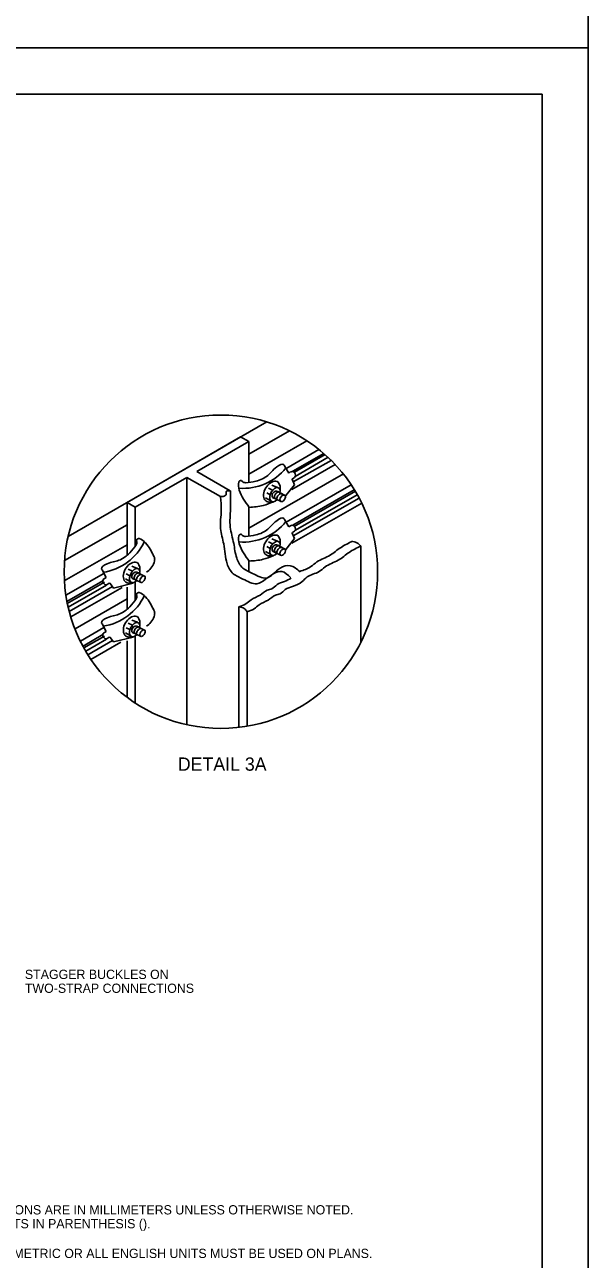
# Model space of a CAD drawing. Extents: x 650495 to 651400, y 297864 to 299646.
# Drawn here: x 651153.6 to 651336.3, y 298064.9 to 298465.1 of the extents above; entities that cross this region are included whole.
import ezdxf

# ---------------------------------------------------------------- set-up
doc = ezdxf.new("R2010")
doc.units = 0
for name, color, linetype in [('1', 7, 'Continuous'), ('2', 7, 'Continuous'), ('PLT-BNDY', 7, 'Continuous')]:
    doc.layers.add(name, color=color, linetype=linetype)

msp = doc.modelspace()

# ---------------------------------------------------------------- linework, layer by layer
at = {"layer": '1'}
for p in [(650535.31, 298442.63), (651321.31, 297878.63)]:
    msp.add_line(p, (651321.31, 298442.63), dxfattribs=at)
at = {"layer": '2'}
for p, q in [((651167.69, 298299.25), (651232.06, 298336.38)), ((651226.31, 298325.88), (651239.44, 298333.5)), ((651239.44, 298333.5), (651239.44, 298333.5)), ((651186.81, 298310.25), (651223.56, 298331.5)), ((651226.31, 298330), (651209.44, 298320.25)), ((651223.56, 298331.5), (651226.31, 298330)), ((651226.31, 298319.38), (651245.06, 298330.25)), ((651226.31, 298330), (651226.31, 298316.79)), ((651238.56, 298321.4), (651248.94, 298327.38)), ((651250.56, 298326.13), (651240.59, 298320.4)), ((651241.04, 298320.01), (651251.06, 298325.75)), ((651241.31, 298318.63), (651251.94, 298324.88)), ((651237.81, 298322.13), (651239.19, 298319.75)), ((651240.19, 298314.45), (651254.31, 298322.5)), ((651240.69, 298316.88), (651252.94, 298323.88)), ((651206.19, 298318.38), (651189.44, 298308.75)), ((651206.19, 298318.38), (651206.19, 298238.13)), ((651217.05, 298312.12), (651206.19, 298318.38)), ((651209.44, 298320.25), (651220.25, 298314.02)), ((651226.31, 298301.95), (651256.94, 298319.5)), ((651240.31, 298317.75), (651241.06, 298316)), ((651232.06, 298313.38), (651233.19, 298312.75)), ((651232.69, 298314.88), (651233.94, 298314.25)), ((651233.19, 298313.75), (651233.19, 298313.75)), ((651233.69, 298315.88), (651235.56, 298315.13)), ((651235.44, 298313.88), (651237.81, 298312.63)), ((651241.06, 298316), (651238.31, 298312.44)), ((651238.34, 298303.84), (651259.44, 298316)), ((651240.54, 298302.9), (651260.44, 298314.38)), ((651241, 298302.43), (651260.81, 298313.88)), ((651241.44, 298301.22), (651261.44, 298312.75)), ((651186.81, 298310.25), (651186.81, 298293.25)), ((651189.44, 298308.75), (651186.81, 298310.25)), ((651189.44, 298308.75), (651189.44, 298296.13)), ((651226.31, 298308.65), (651226.31, 298299.24)), ((651231.69, 298311.75), (651233.44, 298310.75)), ((651233.94, 298311.88), (651236.56, 298310.63)), ((651240.19, 298297.02), (651262.92, 298309.98)), ((651240.69, 298299.45), (651262.07, 298311.67)), ((651237.81, 298304.7), (651239.19, 298302.32)), ((651166.56, 298291.38), (651186.81, 298303)), ((651232.69, 298297.45), (651233.94, 298296.82)), ((651233.69, 298298.45), (651235.56, 298297.7)), ((651241.06, 298298.57), (651238.31, 298295.01)), ((651240.31, 298300.32), (651241.06, 298298.57)), ((651166.44, 298284.88), (651186.81, 298296.5)), ((651231.69, 298294.32), (651233.44, 298293.32)), ((651232.06, 298295.95), (651233.19, 298295.32)), ((651233.19, 298296.32), (651233.19, 298296.32)), ((651233.94, 298294.45), (651236.56, 298293.2)), ((651235.44, 298296.45), (651237.81, 298295.2)), ((651262.56, 298295.99), (651262.56, 298264.75)), ((651187.19, 298288.63), (651188.56, 298288)), ((651188.31, 298289.63), (651190.19, 298288.88)), ((651226.31, 298287.77), (651226.31, 298291.22)), ((651166.94, 298280.13), (651179.31, 298287.25)), ((651167.31, 298278.13), (651178.94, 298284.88)), ((651178.69, 298288.38), (651180.06, 298285.88)), ((651186.31, 298285.5), (651187.94, 298284.5)), ((651186.56, 298287.13), (651187.69, 298286.5)), ((651187.69, 298287.5), (651187.69, 298287.5)), ((651188.56, 298285.63), (651191.19, 298284.38)), ((651189.94, 298287.63), (651192.44, 298286.38)), ((651167.44, 298277.5), (651179.44, 298284.38)), ((651167.69, 298276.25), (651180.19, 298283.38)), ((651168.06, 298274.88), (651182.06, 298283)), ((651168.56, 298273.13), (651185.22, 298282.68)), ((651181.31, 298284), (651182.44, 298282.5)), ((651182.44, 298282.5), (651188.76, 298284.05)), ((651186.81, 298282.77), (651186.81, 298275.75)), ((651189.44, 298278.63), (651189.44, 298284.37)), ((651169.94, 298269.25), (651186.81, 298279)), ((651223.06, 298276.43), (651223.06, 298237.31)), ((651225.69, 298274.81), (651225.69, 298237.68)), ((651171.69, 298265.25), (651179.31, 298269.75)), ((651178.69, 298270.88), (651180.06, 298268.38)), ((651186.56, 298269.63), (651187.69, 298269)), ((651187.19, 298271.13), (651188.56, 298270.5)), ((651187.69, 298270), (651187.69, 298270)), ((651188.31, 298272.13), (651190.19, 298271.38)), ((651189.94, 298270.13), (651192.44, 298268.88)), ((651172.56, 298263.63), (651178.94, 298267.38)), ((651172.81, 298263.13), (651179.44, 298266.88)), ((651173.44, 298262), (651180.19, 298265.88)), ((651174.06, 298260.88), (651182.06, 298265.5)), ((651175.06, 298259.38), (651184.79, 298264.94)), ((651181.31, 298266.5), (651182.44, 298265)), ((651182.44, 298265), (651188.78, 298266.56)), ((651186.31, 298268), (651187.94, 298267)), ((651186.81, 298265.36), (651186.81, 298247.13)), ((651188.56, 298268.13), (651191.19, 298266.88)), ((651189.44, 298266.89), (651189.44, 298245.25))]:
    msp.add_line(p, q, dxfattribs=at)
msp.add_circle((651217.22, 298287.78), 50.81, dxfattribs=at)
for centre, radius, start, end in [((651224.4, 298332.68), 17.87, 265.8316, 321.1473), ((651233.11, 298314.77), 3.36, 347.3784, 39.1914), ((651235.37, 298314.06), 1.04, 326.3099, 77.2929), ((651224.4, 298315.25), 17.87, 265.8316, 321.1473), ((651176.3, 298305.25), 17.87, 278.8526, 334.1683), ((651235.37, 298296.63), 1.04, 326.3099, 77.2929), ((651233.11, 298297.35), 3.36, 347.3784, 39.1914), ((651189.9, 298287.81), 1.04, 326.3099, 77.2929), ((651187.64, 298288.52), 3.36, 347.3784, 39.1914), ((651176.3, 298287.75), 17.87, 278.8526, 334.8505), ((651187.64, 298271.02), 3.36, 347.3784, 39.1914), ((651189.9, 298270.31), 1.04, 326.3099, 77.2929)]:
    msp.add_arc(centre, radius, start, end, dxfattribs=at)
for centre, major_axis, ratio, start_param, end_param in [((651233.87, 298313.73), (-1.86, -3.16), 0.66529, 3.112342, 6.959485), ((651234.82, 298312.78), (-1.19, -2.21), 0.589639, 3.346784, 7.343149), ((651234.7, 298312.88), (-0.705, -0.983), 0.589639, 3.251776, 6.551705), ((651235.49, 298312.57), (-0.705, -0.983), 0.589639, 3.009528, 6.308804), ((651236.28, 298312.05), (-0.705, -0.983), 0.589639, 3.009528, 6.308804), ((651233.87, 298296.3), (-1.86, -3.16), 0.66529, 3.112342, 6.959485), ((651234.82, 298295.35), (-1.19, -2.21), 0.589639, 3.346784, 7.343149), ((651234.7, 298295.46), (-0.705, -0.983), 0.589639, 3.251776, 6.551705), ((651235.49, 298295.14), (-0.705, -0.983), 0.589639, 3.009528, 6.308804), ((651236.28, 298294.62), (-0.705, -0.983), 0.589639, 3.009528, 6.308804), ((651188.4, 298287.48), (-1.86, -3.16), 0.66529, 3.112342, 7.061537), ((651189.35, 298286.53), (-1.19, -2.21), 0.589639, 3.346784, 7.304711), ((651189.23, 298286.63), (-0.705, -0.983), 0.589639, 3.251776, 6.551705), ((651190.02, 298286.32), (-0.705, -0.983), 0.589639, 3.009528, 6.308804), ((651190.82, 298285.8), (-0.705, -0.983), 0.589639, 3.009528, 6.308804), ((651188.4, 298269.98), (-1.86, -3.16), 0.66529, 3.112342, 6.979702), ((651189.35, 298269.03), (-1.19, -2.21), 0.589639, 3.346784, 7.348359), ((651189.23, 298269.13), (-0.705, -0.983), 0.589639, 3.251776, 6.551705), ((651190.02, 298268.82), (-0.705, -0.983), 0.589639, 3.009528, 6.308804), ((651190.82, 298268.3), (-0.705, -0.983), 0.589639, 3.009528, 6.308804)]:
    msp.add_ellipse(centre, major_axis=major_axis, ratio=ratio, start_param=start_param, end_param=end_param, dxfattribs=at)
for centre in [(651237.27, 298311.58), (651237.27, 298294.15), (651191.81, 298285.33), (651191.81, 298267.83)]:
    msp.add_ellipse(centre, major_axis=(-0.705, -0.983), ratio=0.589639, dxfattribs=at)
for points in [[(651225.19, 298316.63), (651228.56, 298317.13), (651232.44, 298319), (651235.31, 298321.75), (651237.69, 298322.38), (651237.81, 298322.13)], [(651226.38, 298308.65), (651223.19, 298314.25), (651223.06, 298316.88), (651223.19, 298317.13), (651223.44, 298317.25)], [(651223.44, 298317.25), (651223.56, 298317.38), (651224.19, 298317), (651225.19, 298316.63)], [(651239.19, 298319.75), (651240.69, 298320.25), (651241.31, 298318.63), (651240.31, 298317.63), (651240.31, 298317.5)], [(651220.32, 298314.01), (651218.98, 298313.81), (651218.9, 298312.75), (651218.27, 298312.28), (651217.13, 298312.12)], [(651242.92, 298287.71), (651239.68, 298289.72), (651236.44, 298288.97), (651231.98, 298285.74), (651227.48, 298287.24), (651224.32, 298288.98), (651222.35, 298292.21), (651221.37, 298296.94), (651220.26, 298302.27), (651220.34, 298308.19), (651220.32, 298314.01)], [(651239.81, 298285.88), (651237, 298287.86), (651231.71, 298285.34), (651228.87, 298283.91), (651224.37, 298285.41), (651221.22, 298287.15), (651219.24, 298290.39), (651218.13, 298296.78), (651217.11, 298301.79), (651217.34, 298307.69), (651217.11, 298312.11)], [(651234.14, 298310.38), (651230.94, 298309.25), (651226.31, 298308.64)], [(651225.19, 298299.2), (651228.56, 298299.7), (651232.44, 298301.57), (651235.31, 298304.32), (651237.69, 298304.95), (651237.81, 298304.7)], [(651239.19, 298302.32), (651240.69, 298302.82), (651241.31, 298301.2), (651240.31, 298300.2), (651240.31, 298300.07)], [(651190.06, 298298.38), (651189.94, 298298.25), (651189.94, 298297.5), (651189.81, 298296.5)], [(651195.44, 298292.88), (651192.81, 298297.13), (651190.69, 298298.5), (651190.44, 298298.5), (651190.06, 298298.38)], [(651226.38, 298291.23), (651223.19, 298296.82), (651223.06, 298299.45), (651223.19, 298299.7), (651223.44, 298299.82)], [(651223.44, 298299.82), (651223.56, 298299.95), (651224.19, 298299.57), (651225.19, 298299.2)], [(651242.82, 298287.88), (651246.39, 298289.44), (651248.36, 298290.94), (651252.62, 298293.15), (651256.17, 298295.68), (651259.92, 298297.67)], [(651262.6, 298295.95), (651261.72, 298296.97), (651259.97, 298297.58)], [(651189.81, 298296.5), (651187.69, 298293.88), (651184.19, 298291.5), (651180.31, 298290.38), (651178.56, 298288.63), (651178.69, 298288.38)], [(651193.06, 298287.63), (651193.44, 298287.88), (651195.69, 298291.25), (651195.69, 298292.38), (651195.19, 298293.13)], [(651225.69, 298274.81), (651227.96, 298275.75), (651229.62, 298277.09), (651232.54, 298278.59), (651234.91, 298280.17), (651236.4, 298280.64), (651238.06, 298281.98), (651240.43, 298283.01), (651243.59, 298284.59), (651245.16, 298286.09), (651249.03, 298287.82), (651251, 298289.32), (651255.26, 298291.53), (651258.81, 298294.06), (651262.56, 298296.06)], [(651234.14, 298292.95), (651230.94, 298291.82), (651226.31, 298291.22)], [(651180.06, 298285.88), (651178.94, 298284.88), (651180.06, 298283.5), (651181.31, 298284), (651181.44, 298283.88)], [(651223.05, 298276.42), (651225.32, 298277.36), (651226.98, 298278.71), (651229.9, 298280.21), (651232.27, 298281.78), (651233.76, 298282.26), (651235.42, 298283.6), (651237.79, 298284.63), (651240.02, 298285.71)], [(651190.06, 298280.88), (651189.94, 298280.75), (651189.94, 298280), (651189.81, 298279)], [(651195.44, 298275.38), (651192.81, 298279.63), (651190.69, 298281), (651190.44, 298281), (651190.06, 298280.88)], [(651189.81, 298279), (651187.69, 298276.38), (651184.19, 298274), (651180.31, 298272.88), (651178.56, 298271.13), (651178.69, 298270.88)], [(651193.06, 298270.13), (651193.44, 298270.38), (651195.69, 298273.75), (651195.69, 298274.88), (651195.19, 298275.63)], [(651225.69, 298274.81), (651224.81, 298275.82), (651223.06, 298276.43)], [(651180.06, 298268.38), (651178.94, 298267.38), (651180.06, 298266), (651181.31, 298266.5), (651181.44, 298266.38)]]:
    msp.add_spline(points, degree=3, dxfattribs=at)
at = {"layer": 'PLT-BNDY'}
for points in [[(650495.31, 299051.63), (651336.31, 299051.63), (651336.31, 298457.63), (650495.31, 298457.63)], [(650495.31, 298457.63), (651336.31, 298457.63), (651336.31, 297863.63), (650495.31, 297863.63)]]:
    msp.add_lwpolyline(points, close=True, dxfattribs=at)

# ---------------------------------------------------------------- texts
at = {"layer": '2'}
for s, height, p in [('DETAIL 3A', 4.3, (651203.26, 298223.27)), ('STAGGER BUCKLES ON', 3, (651153.69, 298155.75)), ('TWO-STRAP CONNECTIONS', 3, (651153.69, 298151.25)), ('1.  ALL DIMENSIONS ARE IN MILLIMETERS UNLESS OTHERWISE NOTED.', 3, (651119.74, 298079.42)), ('    ENGLISH UNITS IN PARENTHESIS ().', 3, (651119.74, 298074.92)), ('2.  EITHER ALL METRIC OR ALL ENGLISH UNITS MUST BE USED ON PLANS.', 3, (651120.31, 298065.29))]:
    msp.add_text(s, height=height, dxfattribs=at).set_placement(p)

doc.saveas('drawing.dxf')
